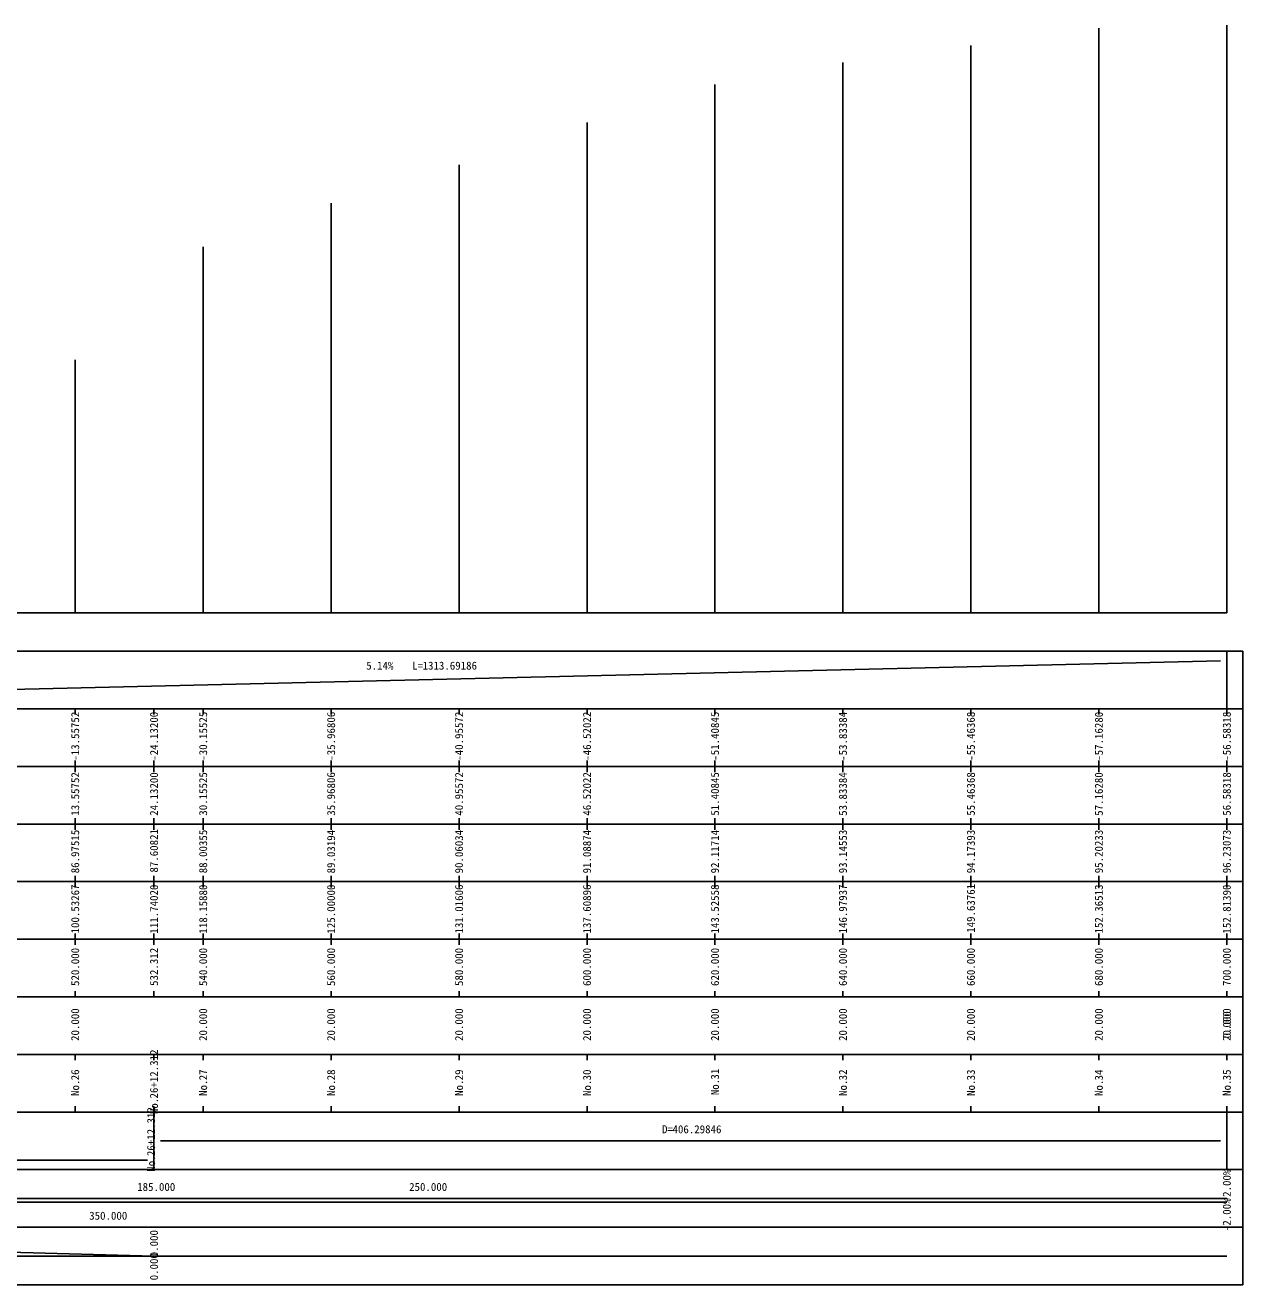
# Model space of a CAD drawing. Extents: x 322 to 703, y -44 to 161.
# Drawn here: x 512.2 to 702.5, y -44 to 152.8 of the extents above; entities that cross this region are included whole.
import ezdxf

# ---------------------------------------------------------------- set-up
doc = ezdxf.new("R2010")
doc.units = 0
for name, color, linetype in [('Default', 7, 'Continuous'), ('設計図面_縦断図_グリッド', 7, 'Continuous'), ('設計図面_縦断図_テキスト', 7, 'Continuous')]:
    doc.layers.add(name, color=color, linetype=linetype)

msp = doc.modelspace()

# ---------------------------------------------------------------- linework, layer by layer
at = {"layer": 'Default'}
for p, q in [((700, 55), (700, 46)), ((532.31, -17), (532.31, -26)), ((532.31, -17), (532.31, -26)), ((700, -17), (700, -26)), ((450, -31.1), (700, -31.1))]:
    msp.add_line(p, q, dxfattribs=at)
at = {"layer": '設計図面_縦断図_グリッド'}
for p, q in [((680, 61), (680, 152.37)), ((700, 61), (700, 152.81)), ((660, 61), (660, 149.64)), ((640, 61), (640, 146.98)), ((620, 61), (620, 143.53)), ((600, 61), (600, 137.61)), ((580, 61), (580, 131.02)), ((560, 61), (560, 125)), ((540, 61), (540, 118.16)), ((520, 61), (520, 100.53)), ((350, 61), (700, 61)), ((702.5, 55), (322.5, 55)), ((446, 47.5), (699, 53.5)), ((702.5, 46), (702.5, 55)), ((322.5, 46), (702.5, 46)), ((702.5, 46), (322.5, 46)), ((520, 46), (520, 45.1)), ((532.31, 46), (532.31, 45.1)), ((540, 46), (540, 45.1)), ((560, 46), (560, 45.1)), ((580, 46), (580, 45.1)), ((600, 46), (600, 45.1)), ((620, 46), (620, 45.1)), ((640, 46), (640, 45.1)), ((660, 46), (660, 45.1)), ((680, 46), (680, 45.1)), ((700, 46), (700, 45.1)), ((702.5, 37), (702.5, 46)), ((520, 37), (520, 37.9)), ((532.31, 37), (532.31, 37.9)), ((540, 37), (540, 37.9)), ((560, 37), (560, 37.9)), ((580, 37), (580, 37.9)), ((600, 37), (600, 37.9)), ((620, 37), (620, 37.9)), ((640, 37), (640, 37.9)), ((660, 37), (660, 37.9)), ((680, 37), (680, 37.9)), ((700, 37), (700, 37.9)), ((322.5, 37), (702.5, 37)), ((702.5, 37), (322.5, 37)), ((520, 37), (520, 36.1)), ((532.31, 37), (532.31, 36.1)), ((540, 37), (540, 36.1)), ((560, 37), (560, 36.1)), ((580, 37), (580, 36.1)), ((600, 37), (600, 36.1)), ((620, 37), (620, 36.1)), ((640, 37), (640, 36.1)), ((660, 37), (660, 36.1)), ((680, 37), (680, 36.1)), ((700, 37), (700, 36.1)), ((702.5, 28), (702.5, 37)), ((322.5, 28), (702.5, 28)), ((702.5, 28), (322.5, 28)), ((520, 28), (520, 28.9)), ((520, 28), (520, 27.1)), ((532.31, 28), (532.31, 28.9)), ((532.31, 28), (532.31, 27.1)), ((540, 28), (540, 28.9)), ((540, 28), (540, 27.1)), ((560, 28), (560, 28.9)), ((560, 28), (560, 27.1)), ((580, 28), (580, 28.9)), ((580, 28), (580, 27.1)), ((600, 28), (600, 28.9)), ((600, 28), (600, 27.1)), ((620, 28), (620, 28.9)), ((620, 28), (620, 27.1)), ((640, 28), (640, 28.9)), ((640, 28), (640, 27.1)), ((660, 28), (660, 28.9)), ((660, 28), (660, 27.1)), ((680, 28), (680, 28.9)), ((680, 28), (680, 27.1)), ((700, 28), (700, 28.9)), ((700, 28), (700, 27.1)), ((702.5, 19), (702.5, 28)), ((520, 19), (520, 19.9)), ((532.31, 19), (532.31, 19.9)), ((540, 19), (540, 19.9)), ((560, 19), (560, 19.9)), ((580, 19), (580, 19.9)), ((600, 19), (600, 19.9)), ((620, 19), (620, 19.9)), ((640, 19), (640, 19.9)), ((660, 19), (660, 19.9)), ((680, 19), (680, 19.9)), ((700, 19), (700, 19.9)), ((322.5, 19), (702.5, 19)), ((702.5, 19), (322.5, 19)), ((520, 19), (520, 18.1)), ((532.31, 19), (532.31, 18.1)), ((540, 19), (540, 18.1)), ((560, 19), (560, 18.1)), ((580, 19), (580, 18.1)), ((600, 19), (600, 18.1)), ((620, 19), (620, 18.1)), ((640, 19), (640, 18.1)), ((660, 19), (660, 18.1)), ((680, 19), (680, 18.1)), ((700, 19), (700, 18.1)), ((702.5, 10), (702.5, 19)), ((322.5, 10), (702.5, 10)), ((702.5, 10), (322.5, 10)), ((520, 10), (520, 10.9)), ((520, 10), (520, 9.1)), ((532.31, 10), (532.31, 10.9)), ((532.31, 10), (532.31, 9.1)), ((540, 10), (540, 10.9)), ((540, 10), (540, 9.1)), ((560, 10), (560, 10.9)), ((560, 10), (560, 9.1)), ((580, 10), (580, 10.9)), ((580, 10), (580, 9.1)), ((600, 10), (600, 10.9)), ((600, 10), (600, 9.1)), ((620, 10), (620, 10.9)), ((620, 10), (620, 9.1)), ((640, 10), (640, 10.9)), ((640, 10), (640, 9.1)), ((660, 10), (660, 10.9)), ((660, 10), (660, 9.1)), ((680, 10), (680, 10.9)), ((680, 10), (680, 9.1)), ((700, 10), (700, 10.9)), ((700, 10), (700, 9.1)), ((702.5, 1), (702.5, 10)), ((322.5, 1), (702.5, 1)), ((702.5, 1), (322.5, 1)), ((520, 1), (520, 1.9)), ((532.31, 1), (532.31, 1.9)), ((540, 1), (540, 1.9)), ((560, 1), (560, 1.9)), ((580, 1), (580, 1.9)), ((600, 1), (600, 1.9)), ((620, 1), (620, 1.9)), ((640, 1), (640, 1.9)), ((660, 1), (660, 1.9)), ((680, 1), (680, 1.9)), ((700, 1), (700, 1.9)), ((702.5, -8), (702.5, 1)), ((322.5, -8), (702.5, -8)), ((702.5, -8), (322.5, -8)), ((520, -8), (520, -8.9)), ((532.31, -8), (532.31, -8.9)), ((540, -8), (540, -8.9)), ((560, -8), (560, -8.9)), ((580, -8), (580, -8.9)), ((600, -8), (600, -8.9)), ((620, -8), (620, -8.9)), ((640, -8), (640, -8.9)), ((660, -8), (660, -8.9)), ((680, -8), (680, -8.9)), ((700, -8), (700, -8.9)), ((702.5, -17), (702.5, -8)), ((322.5, -17), (702.5, -17)), ((702.5, -17), (322.5, -17)), ((520, -17), (520, -16.1)), ((532.31, -17), (532.31, -16.1)), ((540, -17), (540, -16.1)), ((560, -17), (560, -16.1)), ((580, -17), (580, -16.1)), ((600, -17), (600, -16.1)), ((620, -17), (620, -16.1)), ((640, -17), (640, -16.1)), ((660, -17), (660, -16.1)), ((680, -17), (680, -16.1)), ((700, -17), (700, -16.1)), ((702.5, -26), (702.5, -17)), ((533.31, -21.5), (699, -21.5)), ((439.31, -24.5), (531.31, -24.5)), ((322.5, -26), (702.5, -26)), ((702.5, -26), (322.5, -26)), ((702.5, -35), (702.5, -26)), ((350, -30.5), (700, -30.5)), ((350, -31.1), (700, -31.1)), ((322.5, -35), (702.5, -35)), ((702.5, -35), (322.5, -35)), ((702.5, -44), (702.5, -35)), ((432.31, -36.8), (532.31, -39.5)), ((350, -39.5), (700, -39.5)), ((532.31, -39.5), (532.31, -39.5)), ((532.31, -39.5), (700, -39.5)), ((322.5, -44), (702.5, -44))]:
    msp.add_line(p, q, dxfattribs=at)

# ---------------------------------------------------------------- texts
at = {"layer": '設計図面_縦断図_テキスト'}
for s, p in [('5.14%', (565.49, 52.12)), ('L=', (572.67, 52.12)), ('1313.69186', (574.3, 52.12)), ('D=', (611.73, -20.32)), ('406.29846', (613.36, -20.32)), ('185.000', (529.69, -29.33)), ('250.000', (572.19, -29.33)), ('350.000', (522.19, -33.83))]:
    msp.add_text(s, height=1.25, dxfattribs=at).set_placement(p)
for s, p in [('-13.55752', (520.62, 37.89)), ('-24.13200', (532.94, 37.88)), ('-30.15525', (540.62, 37.89)), ('-35.96806', (560.62, 37.89)), ('-40.95572', (580.62, 37.89)), ('-46.52022', (600.62, 37.89)), ('-51.40845', (620.62, 37.89)), ('-53.83384', (640.62, 37.87)), ('-55.46368', (660.62, 37.89)), ('-57.16280', (680.62, 37.88)), ('-56.58318', (700.62, 37.89)), ('13.55752', (520.62, 29.3)), ('24.13200', (532.94, 29.28)), ('30.15525', (540.62, 29.3)), ('35.96806', (560.62, 29.3)), ('40.95572', (580.62, 29.3)), ('46.52022', (600.62, 29.3)), ('51.40845', (620.62, 29.3)), ('53.83384', (640.62, 29.28)), ('55.46368', (660.62, 29.29)), ('57.16280', (680.62, 29.28)), ('56.58318', (700.62, 29.29)), ('86.97515', (520.62, 20.3)), ('87.60821', (532.94, 20.41)), ('88.00355', (540.62, 20.3)), ('89.03194', (560.62, 20.28)), ('90.06034', (580.62, 20.28)), ('91.08874', (600.62, 20.28)), ('92.11714', (620.62, 20.28)), ('93.14553', (640.62, 20.3)), ('94.17393', (660.62, 20.3)), ('95.20233', (680.62, 20.3)), ('96.23073', (700.62, 20.3)), ('100.53267', (520.62, 10.9)), ('111.74020', (532.94, 10.88)), ('118.15880', (540.62, 10.88)), ('125.00000', (560.62, 10.88)), ('131.01606', (580.62, 10.89)), ('137.60896', (600.62, 10.89)), ('143.52558', (620.62, 10.89)), ('146.97937', (640.62, 10.9)), ('149.63761', (660.62, 11)), ('152.36513', (680.62, 10.89)), ('152.81390', (700.62, 10.88)), ('520.000', (520.62, 2.69)), ('532.312', (532.94, 2.7)), ('540.000', (540.62, 2.69)), ('560.000', (560.62, 2.69)), ('580.000', (580.62, 2.69)), ('600.000', (600.62, 2.69)), ('620.000', (620.62, 2.69)), ('640.000', (640.62, 2.69)), ('660.000', (660.62, 2.69)), ('680.000', (680.62, 2.69)), ('700.000', (700.62, 2.69)), ('20.000', (520.62, -5.9)), ('20.000', (540.62, -5.9)), ('20.000', (560.62, -5.9)), ('20.000', (580.62, -5.9)), ('20.000', (600.62, -5.9)), ('20.000', (620.62, -5.9)), ('20.000', (640.62, -5.9)), ('20.000', (660.62, -5.9)), ('20.000', (680.62, -5.9)), ('20.000', (700.62, -5.9)), ('0.000', (700.62, -5.5)), ('26+12.312', (532.94, -14.89)), ('26', (520.62, -12.05)), ('27', (540.62, -12.04)), ('28', (560.62, -12.05)), ('29', (580.62, -12.05)), ('30', (600.62, -12.06)), ('31', (620.62, -11.94)), ('32', (640.62, -12.05)), ('33', (660.62, -12.05)), ('34', (680.62, -12.07)), ('35', (700.62, -12.05)), ('No.', (520.62, -14.49)), ('No.', (540.62, -14.48)), ('No.', (560.62, -14.49)), ('No.', (580.62, -14.48)), ('No.', (600.62, -14.5)), ('No.', (620.62, -14.37)), ('No.', (640.62, -14.49)), ('No.', (660.62, -14.48)), ('No.', (680.62, -14.5)), ('No.', (700.62, -14.48)), ('No.', (532.94, -17.33)), ('26+12.312', (532.49, -23.89)), ('No.', (532.49, -26.33)), ('-2.00%', (700.62, -31.11)), ('-2.00%', (700.62, -35.61)), ('0.000', (532.94, -39.7)), ('0.000', (532.94, -39.7)), ('0.000', (532.94, -43.3)), ('0.000', (532.94, -43.3))]:
    msp.add_text(s, height=1.25, rotation=90, dxfattribs=at).set_placement(p)

doc.saveas('drawing.dxf')
